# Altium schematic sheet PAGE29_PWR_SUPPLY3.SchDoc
size 431 x 304 mm; SheetNumber: 28; SheetTotal: 28
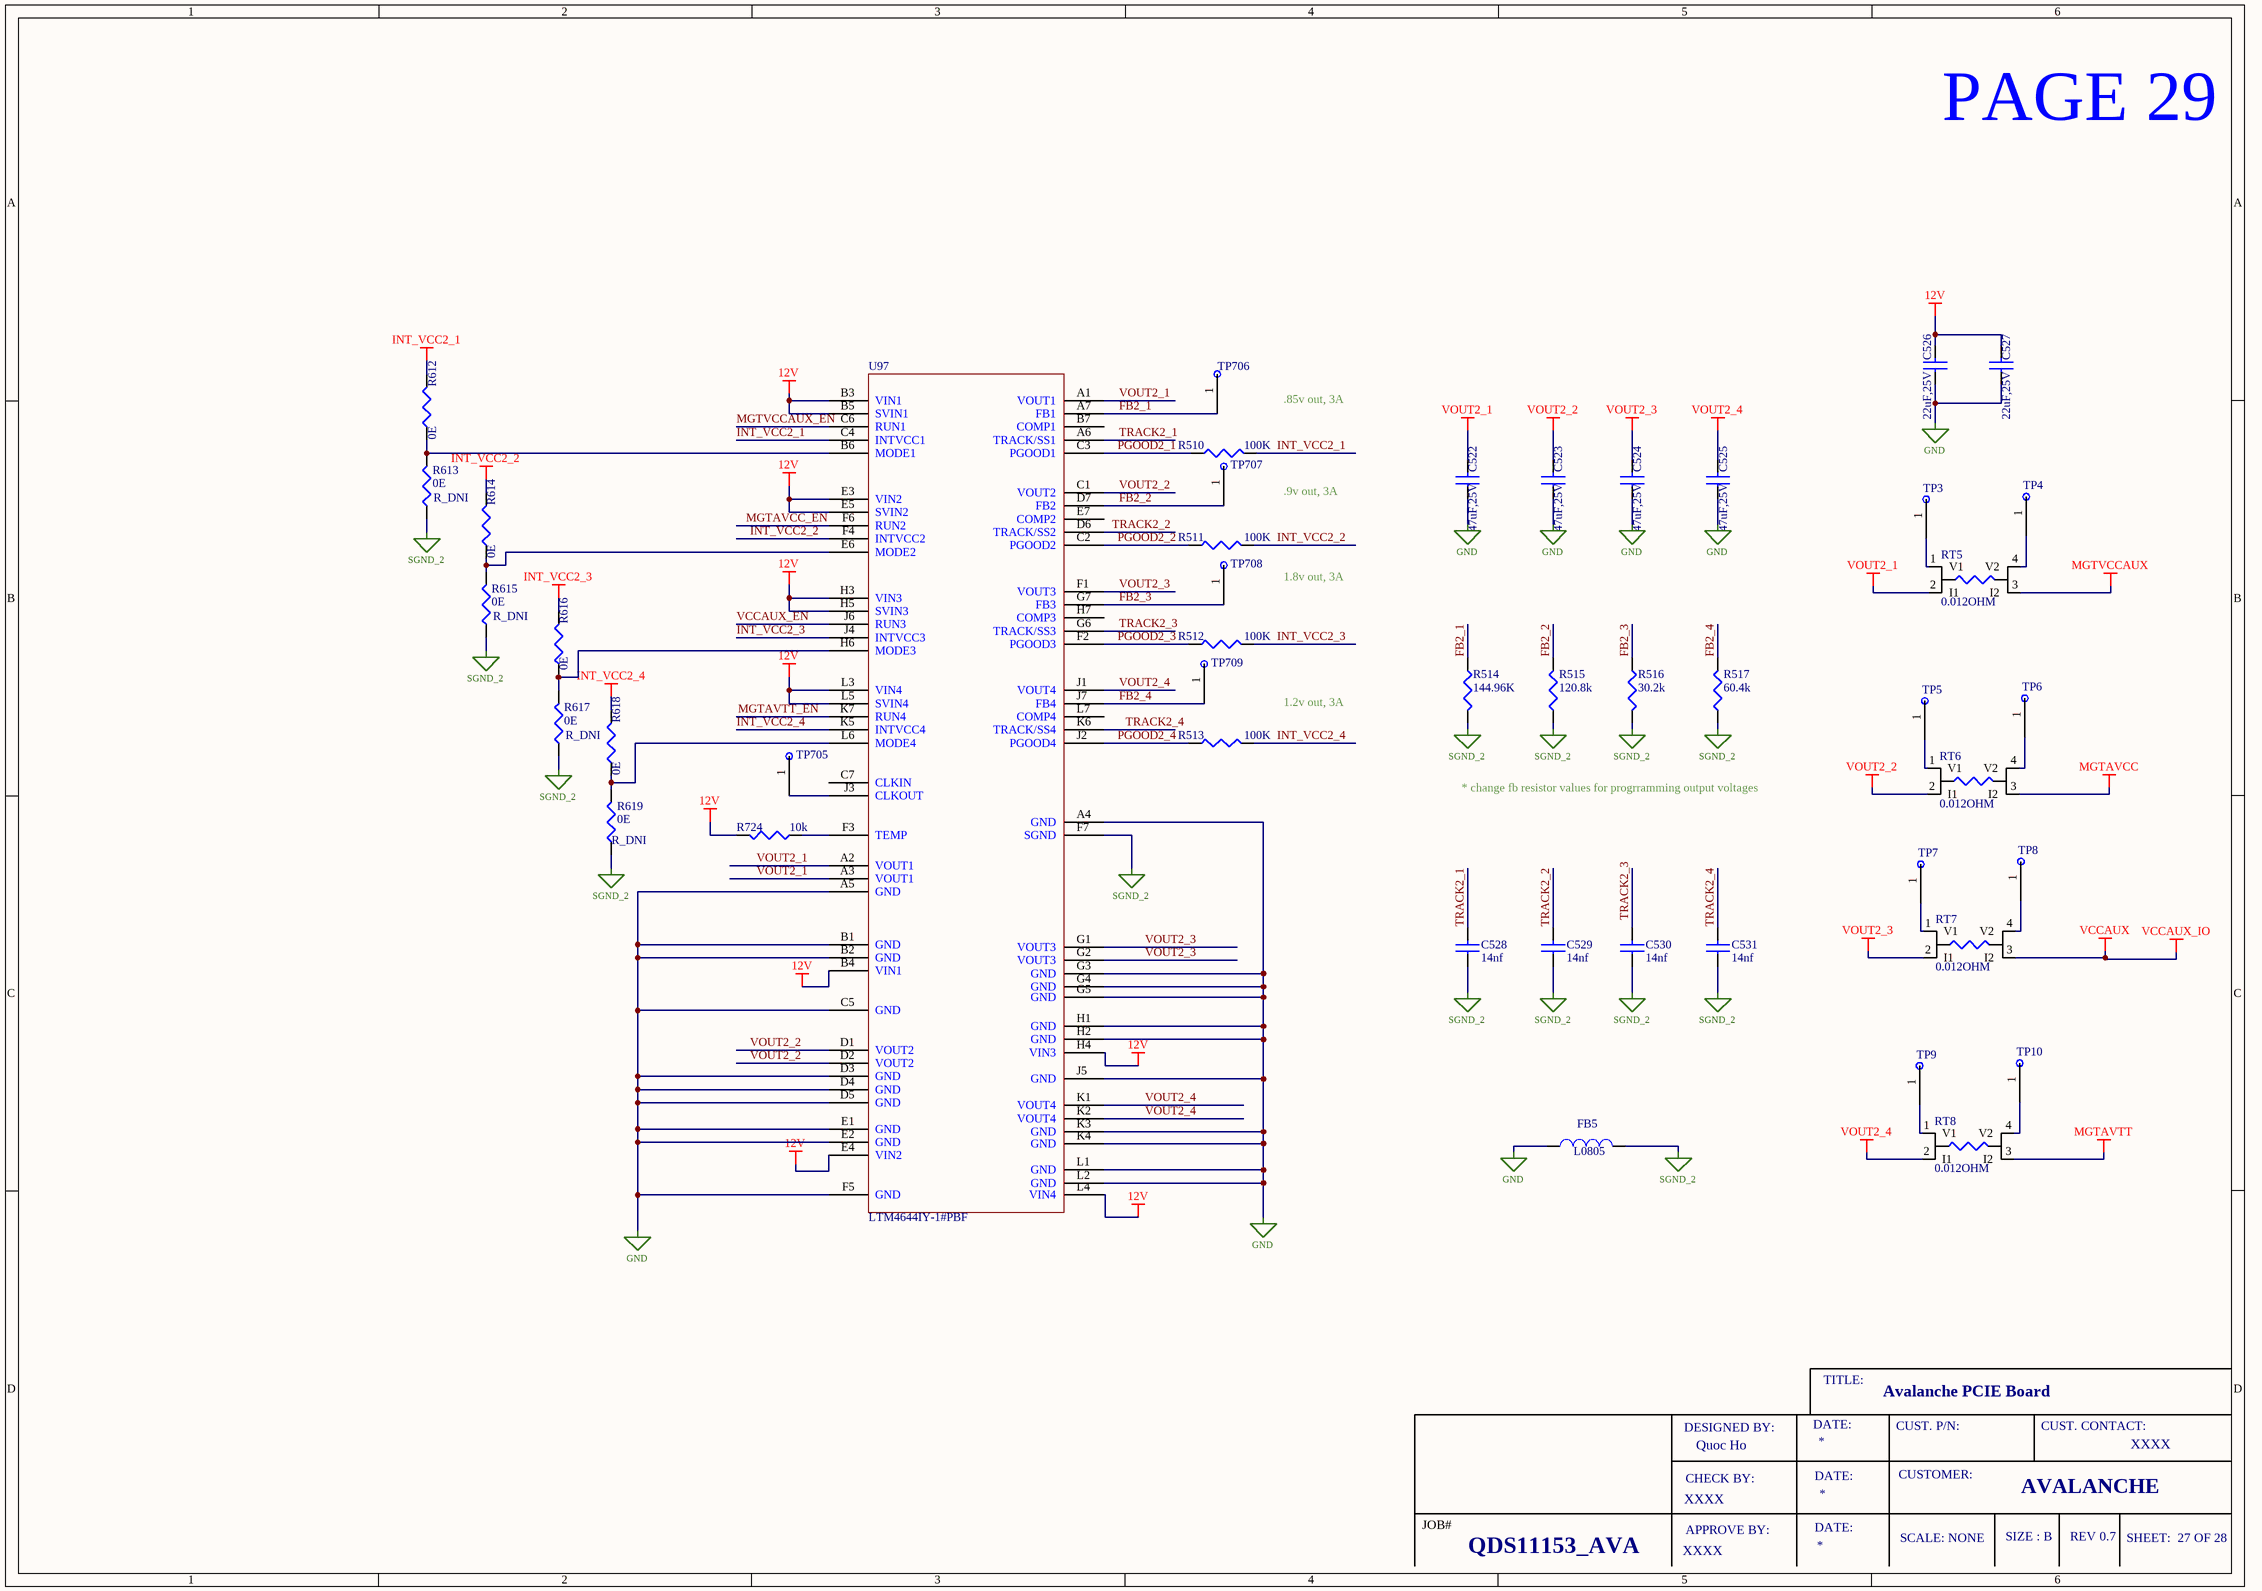
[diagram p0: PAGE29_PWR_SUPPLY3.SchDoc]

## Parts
C522  47uF,25V  [CN_1210]
C523  47uF,25V  [CN_1210]
C524  47uF,25V  [CN_1210]
C525  47uF,25V  [CN_1210]
C526  22uF,25V  [CN_1210]
C527  22uF,25V  [CN_1210]
C528  14nf  [CN_0402]
C529  14nf  [CN_0402]
C530  14nf  [CN_0402]
C531  14nf  [CN_0402]
FB5  L0805  [L0805]
R510  100K  [RN_0402]
R511  100K  [RN_0402]
R512  100K  [RN_0402]
R513  100K  [RN_0402]
R514  144.96K  [RN_0402]
R515  120.8k  [RN_0402]
R516  30.2k  [RN_0402]
R517  60.4k  [RN_0402]
R612  0E  [RN_0402]
R613  0E  [RN_0402]
R614  0E  [RN_0402]
R615  0E  [RN_0402]
R616  0E  [RN_0402]
R617  0E  [RN_0402]
R618  0E  [RN_0402]
R619  0E  [RN_0402]
R724  10k  [RN_0402]
RT5  0.012OHM  [LVK12]
RT6  0.012OHM  [LVK12]
RT7  0.012OHM  [LVK12]
RT8  0.012OHM  [LVK12]
TP3  Tap_point  [MINI_TESTPOINT]  (value not drawn)
TP4  Tap_point  [MINI_TESTPOINT]  (value not drawn)
TP5  Tap_point  [MINI_TESTPOINT]  (value not drawn)
TP6  Tap_point  [MINI_TESTPOINT]  (value not drawn)
TP7  Tap_point  [MINI_TESTPOINT]  (value not drawn)
TP8  Tap_point  [MINI_TESTPOINT]  (value not drawn)
TP9  Tap_point  [MINI_TESTPOINT]  (value not drawn)
TP10  Tap_point  [MINI_TESTPOINT]  (value not drawn)
TP705  Tap_point  [MINI_TESTPOINT]  (value not drawn)
TP706  Tap_point  [MINI_TESTPOINT]  (value not drawn)
TP707  Tap_point  [MINI_TESTPOINT]  (value not drawn)
TP708  Tap_point  [MINI_TESTPOINT]  (value not drawn)
TP709  Tap_point  [MINI_TESTPOINT]  (value not drawn)
U97  LTM4644IY-1#PBF  [BGA77_15X9X1P5_ANALOG]

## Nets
12V: C526.2 C527.2 R724.2 U97.B3(VIN1) U97.B4(VIN1) U97.B5(SVIN1) U97.E3(VIN2) U97.E4(VIN2) U97.E5(SVIN2) U97.H3(VIN3) U97.H4(VIN3) U97.H5(SVIN3) U97.L3(VIN4) U97.L4(VIN4) U97.L5(SVIN4)
GND: C522.1 C523.1 C524.1 C525.1 C526.1 C527.1 FB5.1 U97.A4(GND) U97.A5(GND) U97.B1(GND) U97.B2(GND) U97.C5(GND) U97.D3(GND) U97.D4(GND) U97.D5(GND) U97.E1(GND) U97.E2(GND) U97.F5(GND) U97.G3(GND) U97.G4(GND) U97.G5(GND) U97.H1(GND) U97.H2(GND) U97.J5(GND) U97.K3(GND) U97.K4(GND) U97.L1(GND) U97.L2(GND)
INT_VCC2_1: R510.2 R612.2 U97.C4(INTVCC1)
INT_VCC2_2: R511.2 R614.2 U97.F4(INTVCC2)
INT_VCC2_3: R512.2 R616.2 U97.J4(INTVCC3)
INT_VCC2_4: R513.2 R618.2 U97.K5(INTVCC4)
MGTAVCC: RT6.3(I2)
MGTAVTT: RT8.3(I2)
MGTVCCAUX: RT5.3(I2)
SGND_2: C528.1 C529.1 C530.1 C531.1 FB5.2 R514.2 R515.1 R516.2 R517.1 R613.1 R615.1 R617.1 R619.1 U97.F7(SGND)
VCCAUX: RT7.3(I2)  [also labelled VCCAUX_IO]
VOUT2_1: C522.2 RT5.2(I1) U97.A1(VOUT1) U97.A2(VOUT1) U97.A3(VOUT1)
VOUT2_2: C523.2 RT6.2(I1) U97.C1(VOUT2) U97.D1(VOUT2) U97.D2(VOUT2)
VOUT2_3: C524.2 RT7.2(I1) U97.F1(VOUT3) U97.G1(VOUT3) U97.G2(VOUT3)
VOUT2_4: C525.2 RT8.2(I1) U97.J1(VOUT4) U97.K1(VOUT4) U97.K2(VOUT4)
FB2_1: R514.1 TP706.1 U97.A7(FB1)
FB2_2: R515.2 TP707.1 U97.D7(FB2)
FB2_3: R516.1 TP708.1 U97.G7(FB3)
FB2_4: R517.2 TP709.1 U97.J7(FB4)
MGTAVCC_EN: U97.F6(RUN2)
MGTAVTT_EN: U97.K7(RUN4)
MGTVCCAUX_EN: U97.C6(RUN1)
PGOOD2_1: R510.1 U97.C3(PGOOD1)
PGOOD2_2: R511.1 U97.C2(PGOOD2)
PGOOD2_3: R512.1 U97.F2(PGOOD3)
PGOOD2_4: R513.1 U97.J2(PGOOD4)
TRACK2_1: C528.2 U97.A6(TRACK/SS1)
TRACK2_2: C529.2 U97.D6(TRACK/SS2)
TRACK2_3: C530.2 U97.G6(TRACK/SS3)
TRACK2_4: C531.2 U97.K6(TRACK/SS4)
VCCAUX_EN: U97.J6(RUN3)
NetR612_1: R612.1 R613.2 U97.B6(MODE1)
NetR614_1: R614.1 R615.2 U97.E6(MODE2)
NetR616_1: R616.1 R617.2 U97.H6(MODE3)
NetR618_1: R618.1 R619.2 U97.L6(MODE4)
NetR724_1: R724.1 U97.F3(TEMP)
NetRT5_1: RT5.1(V1) TP3.1
NetRT5_4: RT5.4(V2) TP4.1
NetRT6_1: RT6.1(V1) TP5.1
NetRT6_4: RT6.4(V2) TP6.1
NetRT7_1: RT7.1(V1) TP7.1
NetRT7_4: RT7.4(V2) TP8.1
NetRT8_1: RT8.1(V1) TP9.1
NetRT8_4: RT8.4(V2) TP10.1
NetTP705_1: TP705.1 U97.J3(CLKOUT)

Not connected (* = marked no-connect by the designer): U97 B7(COMP1) C7(CLKIN) E7(COMP2) H7(COMP3) L7(COMP4)

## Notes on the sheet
- PAGE 29
- .85v out, 3A
- .9v out, 3A
- 1.8v out, 3A
- 1.2v out, 3A
- * change fb resistor values for progrramming output voltages
- TITLE:
- Avalanche PCIE Board
- DESIGNED BY:
- CHECK BY:
- Quoc Ho
- DATE:
- CUST. P/N:
- CUSTOMER:
- CUST. CONTACT:
- XXXX
- JOB#
- APPROVE BY:
- SCALE: NONE
- SIZE : B
- AVALANCHE
- REV 0.7
- SHEET:  27 OF 28
- QDS11153_AVA

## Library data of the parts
C522-C525 = CAP: CAP CER 47UF 25V X5R 1210; Manufacturer: KYOCERA AVX; Manufacturer Part Number: KGM32LR51E476MU
C526 C527 = CAP: CAP CER 22UF 25V X5R 1210; Manufacturer: Samsung Electro-Mechanics; Manufacturer Part Number: CL32A226KAJNNNE
C528-C531 = CAP: CAP CER 0402 15NF 50V X7R 5%; Manufacturer Part Number: C0402C153J5RECTU; Manufacturer: KEMET
FB5 = INDUCTOR: FERRITE BEAD 110 OHM 0805 1LN; Manufacturer Part Number: BLM21SP111SZ1D; Manufacturer: Murata Electronics
R510-R513 = RES: RES 100K OHM 1% 1/16W 0402; Manufacturer Part Number: RC0402FR-07100KL; Manufacturer: YAGEO
R514 = RES: RES 143K OHM 1% 1/16W 0402; Manufacturer Part Number: RC0402FR-07143KL; Manufacturer: YAGEO
R515 = RES: RES 120K OHM 1% 1/16W 0402; Manufacturer Part Number: RC0402FR-07120KL; Manufacturer: YAGEO
R516 = RES: RES 30.1K OHM 1% 1/16W 0402; Manufacturer Part Number: RC0402FR-0730K1L; Manufacturer: YAGEO
R517 = RES: RES 60.4K OHM 1% 1/16W 0402; Manufacturer Part Number: RC0402FR-0760K4L; Manufacturer: YAGEO
R612 R614 R616 R618 = RES: RES 0 OHM JUMPER 1/16W 0402; Manufacturer Part Number: RC0402JR-070RL; Manufacturer: YAGEO
R613 R615 R617 R619 = RES: RES 0 OHM JUMPER 1/16W 0402; Manufacturer Part Number: RC0402FR-070RL_DNI; Manufacturer: YAGEO
R724 = RES: RES 10K OHM 1% 1/16W 0402; Manufacturer Part Number: RC0402FR-0710KL; Manufacturer: YAGEO
RT5-RT8 = LVK24: RES 0.012OHM 1% 1/2W 1206; Manufacturer: OHMITE
TP3-TP10 TP705-TP709 = Tap_point: Tap_point 15X25
U97 = LTM4644IY-1#PBF_2908: DC DC CONVERTER 4X0.6-5.5V; Manufacturer: Analog Devices Inc.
